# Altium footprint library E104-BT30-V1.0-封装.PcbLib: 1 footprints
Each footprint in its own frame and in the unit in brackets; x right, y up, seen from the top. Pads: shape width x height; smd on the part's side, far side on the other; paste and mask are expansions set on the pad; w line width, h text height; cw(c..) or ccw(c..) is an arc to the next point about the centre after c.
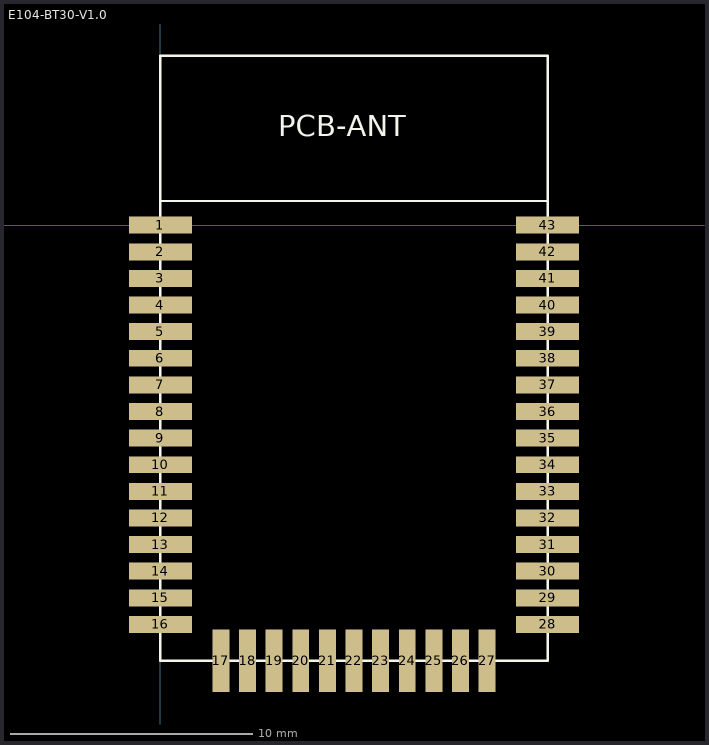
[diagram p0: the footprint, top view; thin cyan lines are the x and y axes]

## E104-BT30-V1.0 [mm] "P43"
pads (43):
  rect 2.6x0.7 smd: 1(0,0) 2(0,-1.1) 3(0,-2.2) 4(0,-3.3) 5(0,-4.4) 6(0,-5.5) 7(0,-6.6) 8(0,-7.7) 9(0,-8.8) 10(0,-9.9) 11(0,-11) 12(0,-12.1) 13(0,-13.2) 14(0,-14.3) 15(0,-15.4) 16(0,-16.5) 28(16,-16.5) 29(16,-15.4) 30(16,-14.3) 31(16,-13.2) 32(16,-12.1) 33(16,-11) 34(16,-9.9) 35(16,-8.8) 36(16,-7.7) 37(16,-6.6) 38(16,-5.5) 39(16,-4.4) 40(16,-3.3) 41(16,-2.2) 42(16,-1.1) 43(16,0)
  rect 0.7x2.6 smd: 17(2.5,-18) 18(3.6,-18) 19(4.7,-18) 20(5.8,-18) 21(6.9,-18) 22(8,-18) 23(9.1,-18) 24(10.2,-18) 25(11.3,-18) 26(12.4,-18) 27(13.5,-18)
Top Layer:
  region: 14.165,6.107
  region: 15.8,1.7
  region: 0.561,0.61
Top Overlay:
  lines w0.1: 0,1 16,1 ; 0,-18 16,-18 16,7 0,7 0,-18
  text "PCB-ANT" at 4.863,3.385 h1.5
